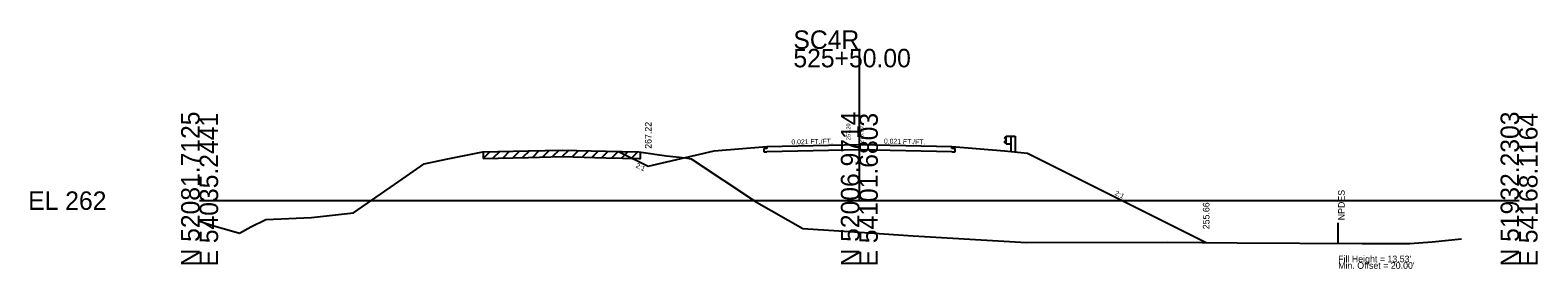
# Model space of a CAD drawing. Extents: x 7498 to 13027, y 90095 to 109625.
# Drawn here: x 9498.3 to 9726.8, y 95594.8 to 95631 of the extents above; entities that cross this region are included whole.
import ezdxf

# ---------------------------------------------------------------- set-up
doc = ezdxf.new("R2010")
doc.units = 0
for name, color, linetype in [('Level 10', 7, 'Continuous'), ('Level 11', 7, 'Continuous'), ('Level 12', 7, 'Continuous'), ('Level 24', 7, 'Continuous'), ('Level 32', 7, 'Continuous'), ('Level 33', 7, 'Continuous'), ('Level 50', 7, 'Continuous'), ('Level 55', 7, 'Continuous'), ('Level 59', 7, 'Continuous'), ('Level 6', 7, 'Continuous'), ('Level 60', 7, 'Continuous'), ('Level 61', 7, 'Continuous'), ('Level 63', 7, 'Continuous'), ('Level 7', 7, 'Continuous')]:
    doc.layers.add(name, color=color, linetype=linetype)

msp = doc.modelspace()

# ---------------------------------------------------------------- linework, layer by layer
at = {"layer": 'Level 11'}
for p, q in [((9609.99, 95613.07), (9609.49, 95613.05)), ((9609.49, 95613.05), (9609.49, 95612.57)), ((9609.99, 95613.37), (9609.99, 95613.07)), ((9637.99, 95613.07), (9637.99, 95613.37)), ((9638.49, 95613.05), (9637.99, 95613.07)), ((9638.49, 95612.57), (9638.49, 95613.05)), ((9609.49, 95612.57), (9609.99, 95612.59)), ((9637.99, 95612.59), (9638.49, 95612.57))]:
    msp.add_line(p, q, dxfattribs=at)
at = {"layer": 'Level 12'}
for p, q in [((9623.99, 95612.88), (9609.99, 95612.59)), ((9637.99, 95612.59), (9623.99, 95612.88))]:
    msp.add_line(p, q, dxfattribs=at)
at = {"layer": 'Level 24'}
for p, q in [((9646.26, 95614.88), (9645.99, 95614.68)), ((9645.99, 95614.68), (9645.99, 95614.63)), ((9645.99, 95614.63), (9646.26, 95614.43)), ((9645.99, 95614.1), (9646.26, 95614.3)), ((9645.99, 95614.05), (9645.99, 95614.1)), ((9646.26, 95613.85), (9645.99, 95614.05)), ((9646.26, 95613.78), (9646.26, 95614.95)), ((9646.26, 95614.95), (9646.93, 95614.95)), ((9646.26, 95613.78), (9646.93, 95613.78)), ((9646.93, 95614.95), (9646.93, 95612.6)), ((9646.93, 95614.95), (9647.6, 95614.95)), ((9647.6, 95614.95), (9647.6, 95612.54))]:
    msp.add_line(p, q, dxfattribs=at)
at = {"layer": 'Level 55'}
msp.add_line((9696.56, 95598.81), (9696.56, 95601.81), dxfattribs=at)
at = {"layer": 'Level 59'}
for p, q in [((9609.99, 95613.37), (9623.99, 95613.66)), ((9623.99, 95613.66), (9637.99, 95613.37))]:
    msp.add_line(p, q, dxfattribs=at)
at = {"layer": 'Level 6'}
for p, q in [((9601.99, 95612.7), (9609.99, 95613.37)), ((9637.99, 95613.37), (9645.99, 95612.7)), ((9645.99, 95612.7), (9649.49, 95612.35))]:
    msp.add_line(p, q, dxfattribs=at)
at = {"layer": 'Level 60'}
for p, q in [((9554.18, 95608.06), (9558.03, 95610.76)), ((9558.03, 95610.76), (9561.36, 95611.46)), ((9561.36, 95611.46), (9566.92, 95612.56)), ((9566.92, 95612.56), (9573.78, 95612.71)), ((9573.78, 95612.71), (9578.94, 95612.84)), ((9578.94, 95612.84), (9585.54, 95612.67)), ((9585.54, 95612.67), (9590.55, 95612.56)), ((9590.55, 95612.56), (9594.75, 95611.98)), ((9594.75, 95611.98), (9597.64, 95611.64)), ((9597.64, 95611.64), (9598.49, 95611.51)), ((9598.49, 95611.51), (9608.38, 95604.91)), ((9547.32, 95603.31), (9554.18, 95608.06)), ((9608.38, 95604.91), (9615.44, 95600.92)), ((9523.99, 95602.05), (9525.99, 95601.38)), ((9531.73, 95601.2), (9534.03, 95602.3)), ((9534.03, 95602.3), (9540.94, 95602.59)), ((9540.94, 95602.59), (9547.32, 95603.31)), ((9525.99, 95601.38), (9530.03, 95600.23)), ((9530.03, 95600.23), (9531.73, 95601.2)), ((9615.44, 95600.92), (9623.99, 95600.35)), ((9623.99, 95600.35), (9632.14, 95599.82)), ((9632.14, 95599.82), (9649.31, 95598.81)), ((9710.81, 95598.9), (9715.26, 95599.38)), ((9649.31, 95598.81), (9670.67, 95598.86)), ((9670.67, 95598.86), (9681.28, 95598.78)), ((9681.28, 95598.78), (9700.22, 95598.64)), ((9700.22, 95598.64), (9707.45, 95598.64)), ((9707.45, 95598.64), (9710.81, 95598.9))]:
    msp.add_line(p, q, dxfattribs=at)
at = {"layer": 'Level 61'}
for p, q in [((9567.98, 95612.58), (9566.95, 95611.56)), ((9566.95, 95612.56), (9566.95, 95611.56)), ((9566.95, 95611.56), (9573.78, 95611.71)), ((9569.48, 95612.61), (9568.45, 95611.59)), ((9570.98, 95612.65), (9569.95, 95611.62)), ((9572.48, 95612.68), (9571.45, 95611.66)), ((9573.98, 95612.71), (9572.95, 95611.69)), ((9573.78, 95611.71), (9578.94, 95611.84)), ((9575.48, 95612.75), (9574.45, 95611.73)), ((9576.98, 95612.79), (9575.95, 95611.76)), ((9578.48, 95612.83), (9577.45, 95611.8)), ((9578.94, 95611.84), (9585.54, 95611.67)), ((9579.93, 95612.81), (9578.95, 95611.84)), ((9581.43, 95612.78), (9580.45, 95611.8)), ((9582.93, 95612.74), (9581.95, 95611.76)), ((9584.43, 95612.7), (9583.45, 95611.73)), ((9585.93, 95612.66), (9584.95, 95611.69)), ((9585.54, 95611.67), (9590.55, 95611.56)), ((9587.43, 95612.63), (9586.45, 95611.65)), ((9588.93, 95612.6), (9587.95, 95611.62)), ((9590.43, 95612.56), (9589.45, 95611.59)), ((9590.55, 95611.56), (9590.81, 95611.53)), ((9590.81, 95611.53), (9590.81, 95612.53))]:
    msp.add_line(p, q, dxfattribs=at)
at = {"layer": 'Level 63'}
for p, q in [((9623.99, 95605.16), (9623.99, 95628.2)), ((9523.99, 95605.16), (9623.99, 95605.16)), ((9623.99, 95605.16), (9723.99, 95605.16))]:
    msp.add_line(p, q, dxfattribs=at)
at = {"layer": 'Level 7'}
for p, q in [((9587.48, 95612.63), (9591.99, 95610.37)), ((9591.99, 95610.37), (9601.99, 95612.7)), ((9649.49, 95612.35), (9676.56, 95598.81))]:
    msp.add_line(p, q, dxfattribs=at)

# ---------------------------------------------------------------- texts
at = {"layer": 'Level 10'}
msp.add_text('257.20', height=0.6, rotation=90, dxfattribs=at).set_placement((9622.63, 95614.34))
at = {"layer": 'Level 32'}
for s, rotation, p in [('0.021 FT./FT.', 1.1916, (9613.7, 95613.69)), ('0.021 FT./FT.', 358.8084, (9627.71, 95613.83)), ('2:1', 333.435, (9590.03, 95610.25)), ('2:1', 333.435, (9662.63, 95606.06))]:
    msp.add_text(s, height=0.75, rotation=rotation, dxfattribs=at).set_placement(p)
at = {"layer": 'Level 33'}
for s, p in [('267.22', (9592.49, 95613.03)), ('255.66', (9677.06, 95600.81))]:
    msp.add_text(s, height=1, rotation=90, dxfattribs=at).set_placement(p)
at = {"layer": 'Level 50'}
msp.add_text(' NPDES', height=1, rotation=90, dxfattribs=at).set_placement((9697.56, 95601.81))
for s, p in [("Fill Height = 13.53' ", (9696.56, 95595.81)), ("Min. Offset = 20.00' ", (9696.56, 95594.81))]:
    msp.add_text(s, height=1, dxfattribs=at).set_placement(p)
at = {"layer": 'Level 59'}
msp.add_text(' 270.50', height=0.6, rotation=90, dxfattribs=at).set_placement((9624.59, 95613.66))
at = {"layer": 'Level 63'}
for s, p in [('SC4R', (9613.99, 95628.2)), ('525+50.00', (9613.99, 95625.4)), ('EL 262', (9498, 95603.76))]:
    msp.add_text(s, height=2.8, dxfattribs=at).set_placement(p)
for s, p in [('N 52081.7125', (9523.99, 95595.16)), ('E 54035.2441', (9526.79, 95595.16)), ('N 52006.9714', (9623.99, 95595.16)), ('E 54101.6803', (9626.79, 95595.16)), ('N 51932.2303', (9723.99, 95595.16)), ('E 54168.1164', (9726.79, 95595.16))]:
    msp.add_text(s, height=2.8, rotation=90, dxfattribs=at).set_placement(p)

doc.saveas('drawing.dxf')
